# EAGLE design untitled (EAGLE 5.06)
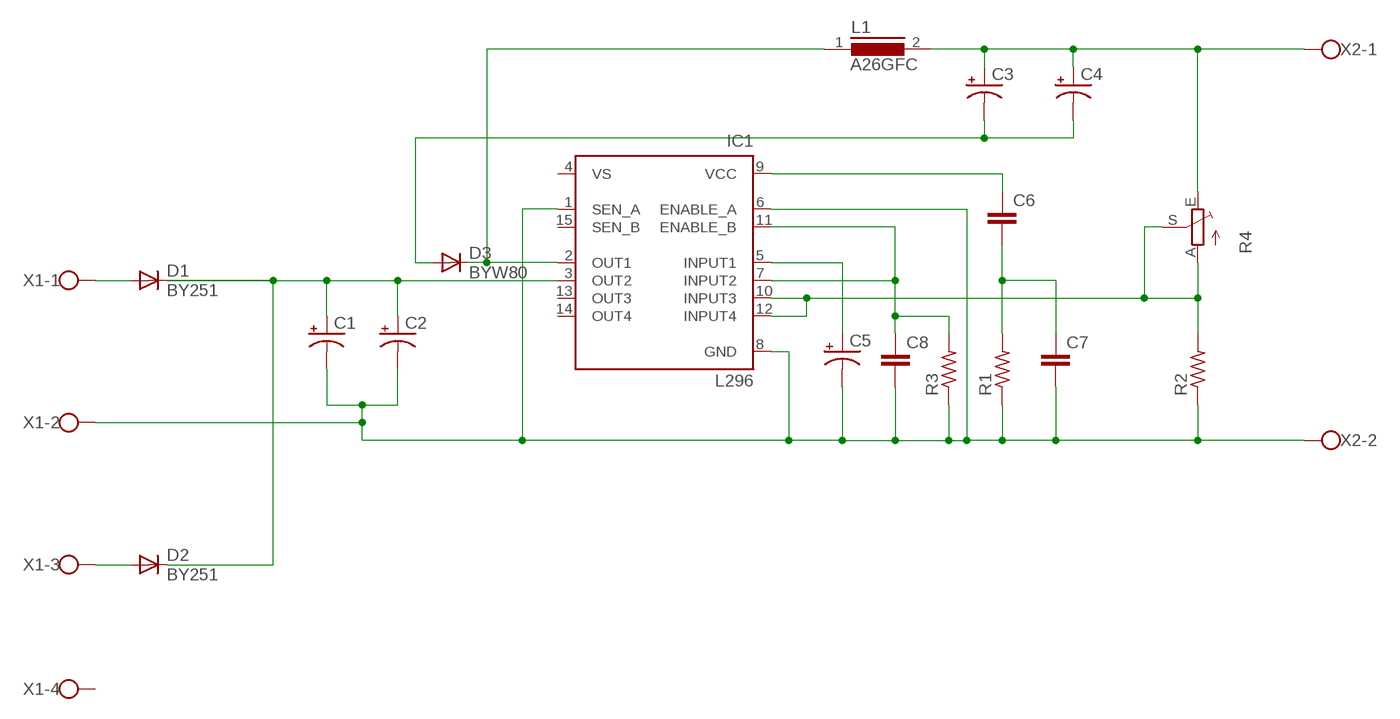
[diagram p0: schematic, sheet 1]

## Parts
C1  CPOL-USE7.5-16  [E7,5-16]
C2  CPOL-USE7.5-16  [E7,5-16]
C3  CPOL-USE5-13  [E5-13]
C4  CPOL-USE5-13  [E5-13]
C5  CPOL-USE5-6  [E5-6]
C6  C-EU050-025X075  [C050-025X075]
C7  C-EU050-025X075  [C050-025X075]
C8  C-EU050-025X075  [C050-025X075]
D1  BY251  [DO201-15]
D2  BY251  [DO201-15]
D3  BYW80  [TO220ACS]
IC1  L296  L298  [MULTIWATT-15]
L1  A26GFC  [A26GFC]
R1  R-US_0207/10  [0207/10]
R2  R-US_0207/10  [0207/10]
R3  R-US_0207/10  [0207/10]
R4  TRIM_EU-CA14H  [CA14H]
X1  W237-4  [W237-4]
X2  W237-102  [W237-102]

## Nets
N$1: D1.A X1.1
N$2: D2.A X1.3
N$3: C1.+ C2.+ D1.C D2.C IC1.3(OUT2)
N$4: D3.C IC1.2(OUT1) L1.1
N$6: C6.2 C7.1 R1.2
N$7: C5.+ IC1.5(INPUT1)
N$8: C1.- C2.- C5.- C7.2 C8.2 IC1.1(SEN_A) IC1.6(ENABLE_A) IC1.8(GND) R1.1 R2.1 R3.1 X1.2 X2.2
N$9: C8.1 IC1.7(INPUT2) IC1.11(ENABLE_B) R3.2
N$10: C6.1 IC1.9(VCC)
N$11: IC1.10(INPUT3) IC1.12(INPUT4) R2.2 R4.A R4.S
N$13: C3.+ C4.+ L1.2 R4.E X2.1
N$14: C3.- C4.- D3.A
Unconnected: IC1.13(OUT3) IC1.14(OUT4) IC1.15(SEN_B) X1.4

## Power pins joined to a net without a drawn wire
VS: IC1.4(VS)

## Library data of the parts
C1-C5 = resistor:CPOL-US: POLARIZED CAPACITOR, American symbol
C6-C8 = resistor:C-EU: CAPACITOR, European symbol
D1 D2 = diode:BY251: DIODE
D3 = diode:BYW80: DIODE
IC1 = st-microelectronics:L298: DUAL FULL-BRIDGE DRIVER
L1 = inductors:A26GFC: INDUCTOR
R1-R3 = resistor:R-US_: RESISTOR, American symbol
R4 = pot:TRIM_EU-: POTENTIOMETER
X1 = con-wago-500:W237-4: WAGO SCREW CLAMP
X2 = con-wago-500:W237-102: WAGO SCREW CLAMP

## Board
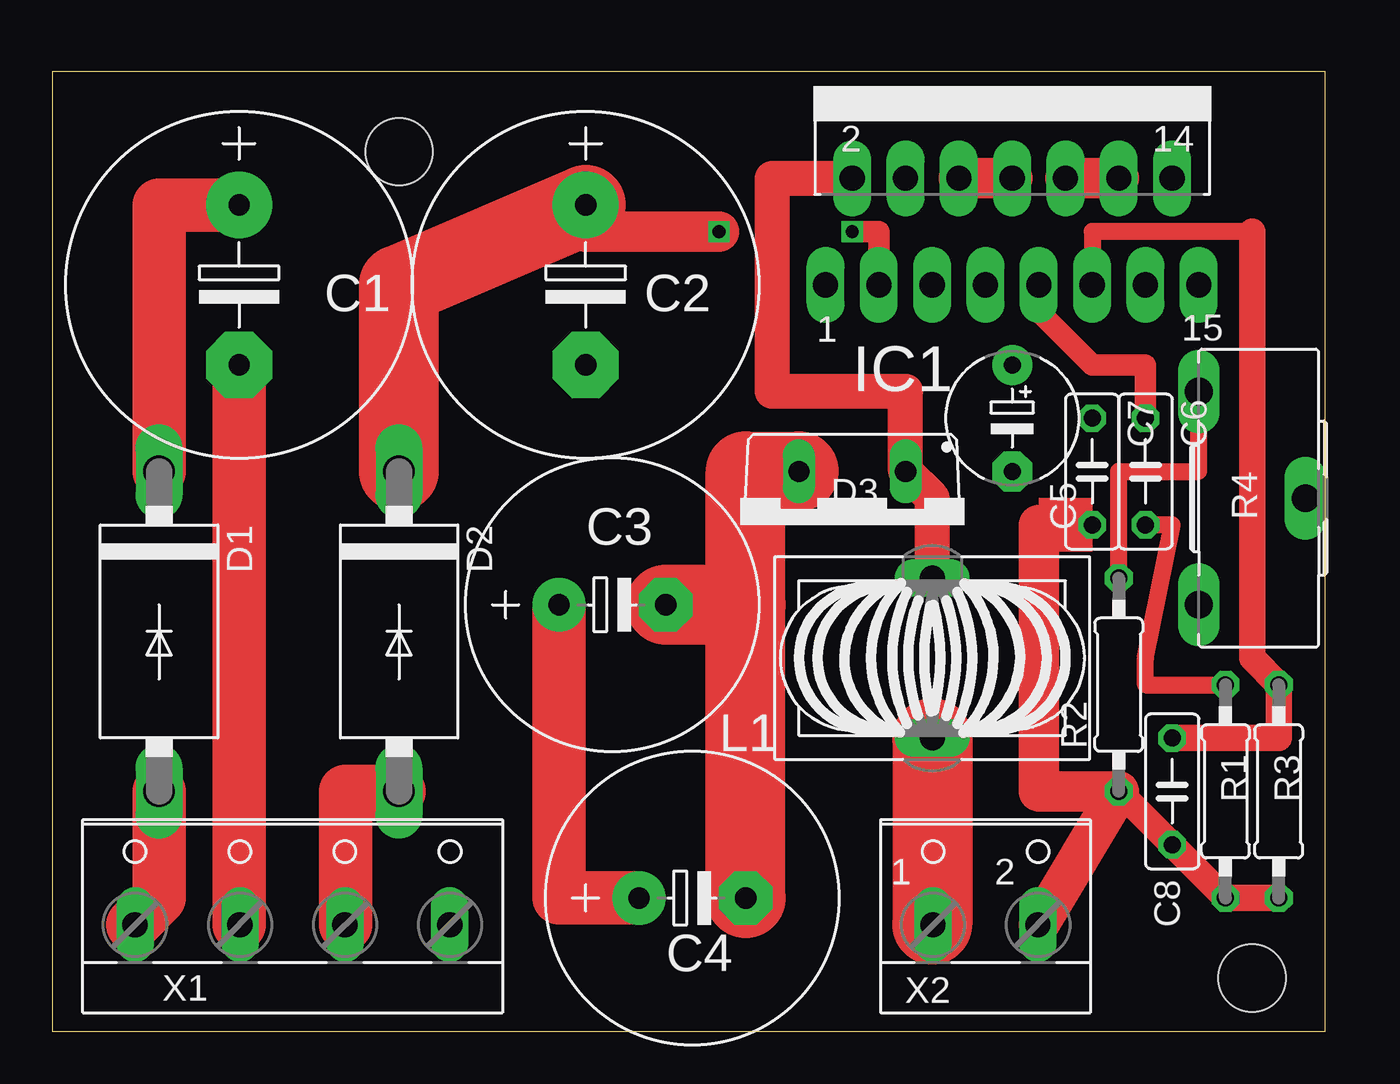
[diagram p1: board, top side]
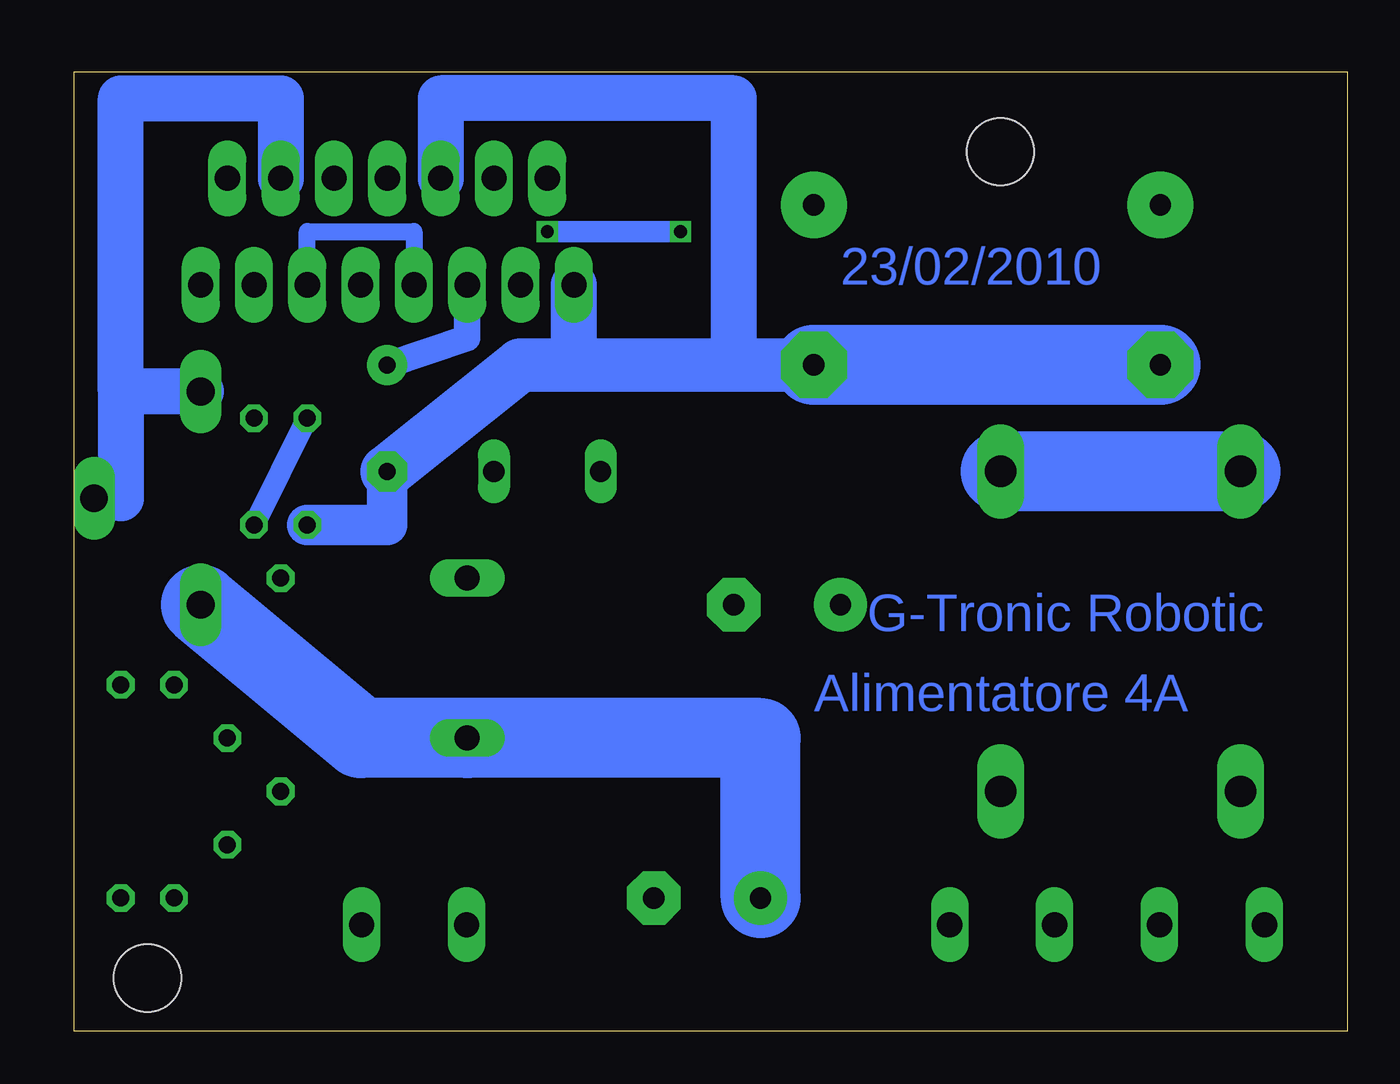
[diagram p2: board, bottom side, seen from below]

Size 60.63 x 45.71 mm. Coordinates in mm from the lower left corner, seen from the top.
Outline: 0,0 60.63,0 60.63,45.71 0,45.71 0,0
Copper layers (1*16): Top 0.035mm / dielectric 1.5mm / Bottom 0.035mm
Design rules "default": minimum track width 10mil, minimum drill 24mil, track to track 8mil, track to pad 8mil, pad to pad 8mil, via to via 8mil, smd to smd 8mil, copper to edge 40mil, drill to drill 8mil, minimum pad ring 10mil, minimum via ring 8mil, stop-mask expansion 4mil, vias tented up to drill 0mil, thermal gap 10mil
Holes 3.2 mm at 57.15,2.54 16.51,41.91

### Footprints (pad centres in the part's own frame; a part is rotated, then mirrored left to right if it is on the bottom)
E7,5-16 = drill 1.016 pad 3.15 round: + -3.81,0 | drill 1.016 pad 3.15 octagon: - 3.81,0
E5-13 = drill 1.016 pad 2.54 round: + -2.54,0 | drill 1.016 pad 2.54 octagon: - 2.54,0
E5-6 = drill 0.813 pad 1.905 round: + -2.54,0 | drill 0.813 pad 1.905 octagon: - 2.54,0
C050-025X075 = drill 0.813 octagon: 1 -2.54,0; 2 2.54,0
DO201-15 = drill 1.499 long: A 7.62,0; C -7.62,0
TO220ACS = drill 1.016 long: A 2.54,-2.54; C -2.54,-2.54
MULTIWATT-15 = drill 1.2 long: 1 -8.89,-7.62; 2 -7.62,-2.54; 3 -6.35,-7.62; 4 -5.08,-2.54; 5 -3.81,-7.62; 6 -2.54,-2.54; 7 -1.27,-7.62; 8 0,-2.54; 9 1.27,-7.62; 10 2.54,-2.54; 11 3.81,-7.62; 12 5.08,-2.54; 13 6.35,-7.62; 14 7.62,-2.54; 15 8.89,-7.62
A26GFC = drill 1.194 long: 1 0,3.81; 2 0,-3.81
0207/10 = drill 0.813 octagon: 1 -5.08,0; 2 5.08,0
CA14H = drill 1.321 long: A -5.08,0; E 5.08,0; S 0,5.08
W237-4 = drill 1.194 long: 1 -7.5,-1.27; 2 -2.5,-1.27; 3 2.5,-1.27; 4 7.5,-1.27
W237-102 = drill 1.194 long: 1 -2.5,-1.27; 2 2.5,-1.27

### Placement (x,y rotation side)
C1  8.89,35.56 270 top
C2  25.4,35.56 270 top
C3  26.67,20.32 0 top
C4  30.48,6.35 0 top
C5  45.72,29.21 270 top
C6  52.07,26.67 270 top
C7  49.53,26.67 270 top
C8  53.34,11.43 270 top
D1  5.08,19.05 270 top
D2  16.51,19.05 270 top
D3  38.1,24.13 180 top
IC1  45.72,43.18 0 top
L1  41.91,17.78 0 top
R1  55.88,11.43 90 top
R2  50.8,16.51 90 top
R3  58.42,11.43 90 top
R4  54.61,25.4 270 top
X1  11.43,6.35 0 top
X2  44.45,6.35 0 top

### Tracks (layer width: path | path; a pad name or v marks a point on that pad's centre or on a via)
N$1
  Top 0.254: X1.1 3.81,5.08
  Top 2.54: 3.81,5.08 5.08,6.35 D1.A
N$2
  Top 0.254: X1.3 13.97,5.08
  Top 2.54: 13.97,5.08 13.97,11.43 D2.A
N$3  (via drill 0.6)
  Top 0.254: C2.+ 25.4,38.1
  Top 1.016: IC1.3 39.37,38.1 v38.1,38.1
  Top 1.93: 25.4,38.1 v31.75,38.1
  Top 2.54: C1.+ 5.08,39.37 D1.C
  Top 3.81: C2.+ 16.51,35.56 D2.C
  Bottom 1.016: v31.75,38.1 v38.1,38.1
  Bottom 3.81: D1.C D2.C
N$4
  Top 1.676: L1.1 41.91,25.4 D3.C 40.64,30.48 34.29,30.48 34.29,40.64 IC1.2
N$6
  Top 0.813: R1.2 52.07,16.51 52.07,17.78 53.34,24.13 C6.2
  Bottom 1.016: C6.2 C7.1
N$7
  Bottom 1.27: IC1.5 41.91,33.02 C5.+
N$8
  Top 0.254: X1.2 8.89,5.08 | 46.99,5.08 X2.2
  Top 1.27: R3.1 R1.1 C8.2 R2.1 | C7.2 46.99,24.13
  Top 1.93: 46.99,5.08 R2.1 46.99,11.43 46.99,24.13 | IC1.6 IC1.8
  Top 2.54: 8.89,5.08 C1.-
  Bottom 1.93: C7.2 45.72,24.13 C5.-
  Bottom 2.184: 36.83,31.75 IC1.1 | IC1.6 43.18,44.45 29.21,44.45 29.21,31.75
  Bottom 2.54: C2.- 29.21,31.75 36.83,31.75 39.37,31.75 C5.-
  Bottom 3.81: C1.- C2.-
N$9
  Top 0.813: 57.15,38.1 49.53,38.1 IC1.11
  Top 1.27: C8.1 58.42,13.97 R3.2 57.15,17.78 57.15,38.1
  Bottom 0.813: IC1.7 44.45,38.1 49.53,38.1 IC1.11
N$10
  Top 1.016: C6.1 52.07,31.75 49.53,31.75 46.99,34.29 IC1.9
N$11
  Top 0.813: R2.2 50.8,26.67 54.61,26.67 54.61,27.94 54.61,29.21 R4.A
  Top 1.93: IC1.12 IC1.10
  Bottom 1.27: 58.42,25.4 R4.S
  Bottom 2.184: 58.42,30.48 58.42,44.45 50.8,44.45 IC1.12 | R4.A 58.42,30.48 | 58.42,30.48 58.42,25.4
N$13
  Top 0.254: 41.91,5.08 X2.1
  Top 2.54: C3.+ 24.13,6.35 C4.+
  Top 3.81: L1.2 41.91,5.08
  Bottom 3.81: R4.E 46.99,13.97 L1.2 27.94,13.97 C4.+
N$14
  Top 3.81: 33.02,20.32 33.02,26.67 D3.A | C4.- 33.02,20.32 | 33.02,20.32 C3.-
(copper drawn outside any net)
  shapes: Top area x1

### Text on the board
Bottom: 23/02/2010 | G-Tronic Robotic | Alimentatore 4A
